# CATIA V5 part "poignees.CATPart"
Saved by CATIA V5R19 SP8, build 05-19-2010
Part number: poignees
Bounding box of the stored display mesh (mm): x -770 to 770, y -400 to 400, z -20 to 70
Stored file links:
  U:\Thinkmotion\Assemblage final\poignees.CATPart
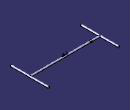
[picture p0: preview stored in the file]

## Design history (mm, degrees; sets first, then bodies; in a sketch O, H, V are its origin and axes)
Body1 (main body)
  Sketch1 on yz-plane, origin (0, 0, 0), H (0, 1, 0), V (0, 0, 1)
    circle A1 centre (0, 0) radius 20
    point P1 (0, 0)
    radius A1 = 20
    coincidence: P1 O
  Pad1: profile Sketch1, direction (1, 0, 0), length 750
  Sketch2 on zx-plane, origin (0, 0, 0), H (-1, 0, 0), V (0, 0, 1)
    circle A1 centre (-750, 0) radius 20
    point P1 (-750, 0)
    reference projected line E1 through (0, 0) direction (-1, 0) from axis of face of Pad1 from Sketch1.A1
    reference projected line E2 (-750, -20) -> (-750, 20) from edge [face of Pad1 from Sketch1.A1 | end face of Pad1]
    coincidence: P1 E1, P1 E2
  Pad2: profile Sketch2, direction (0, 1, 0), length 400, mirrored extent
  Mirror1: of Pad1, Sketch1, about yz-plane
  Mirror2: of Pad2, Sketch2, about yz-plane
  Sketch3 on zx-plane, origin (0, 0, 0), H (-1, 0, 0), V (0, 0, 1)
    line L1 (0, 0) -> (-80, 0)
    point P1 (-80, 0)
    line L2 (-80, 0) -> (-30, 70)
    point P2 (-30, 70)
    line L3 (-30, 70) -> (-30, 30)
    point P3 (-30, 30)
    line L4 (-30, 30) -> (0, 30)
    point P4 (0, 30)
    reference intersected line E1 through (0, 0) direction (0, -1) from yz-plane
    point P7 (80, 0)
    point P8 (30, 70)
    point P9 (30, 30)
    point P10 (0, 30)
    point P11 (0, 0)
    line L5 (0, 0) -> (80, 0)
    line L6 (80, 0) -> (30, 70)
    line L7 (30, 70) -> (30, 30)
    line L8 (30, 30) -> (0, 30)
    length L3 = 40
    length L1 = 80
    length L4 = 30
    distance P4 O = 30
    horizontal: L1 H, L4 H
    vertical: L3 V
    symmetry: P1 P7 E1, P2 P8 E1, P3 P9 E1, P4 P10 E1, O P11 E1, L1 L5 E1, L2 L6 E1, L3 L7 E1, L4 L8 E1
    coincidence: O P11, P4 P10
  Pad3: profile Sketch3, direction (0, 1, 0), length 2, mirrored extent
  Sketch4 on xy-plane, origin (0, 0, 0), H (1, 0, 0), V (0, 1, 0)
    line L1 (-575.1407, -15) -> (-525.1407, -15)
    line L2 (-525.1407, -15) -> (-525.1407, -115)
    line L3 (-525.1407, -115) -> (-575.1407, -115)
    line L4 (-575.1407, -115) -> (-575.1407, -15)
    distance L1 H = 15
    length L3 = 50
    horizontal: L1 H, L3 H
    vertical: L2 V, L4 V
  Pocket1: profile Sketch4, direction (0, 0, -1), length 500, mirrored extent
  Mirror3: of Pocket1, Sketch4, about zx-plane
  Sketch5 on face of Pocket1 from Sketch4.L1, origin (-554.4836, -15, -2.2981), H (1, 0, 0), V (0, 0, 1)
    point P1 (4.343, 2.2981)
    reference intersected line E1 through (0, 2.2981) direction (-1, 0) from xy-plane
    reference projected line E2 (-20.657, 15.5268) -> (-20.657, -10.9307) from edge [face of Mirror1 | face of Pocket1 from Sketch4.L4]
    distance P1 E2 = 25
    coincidence: P1 E1
  Hole1: placed by Sketch5, at (-550.1407, -15, 0) direction (0, 1, 0), diameter 10, through (limit type 3)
